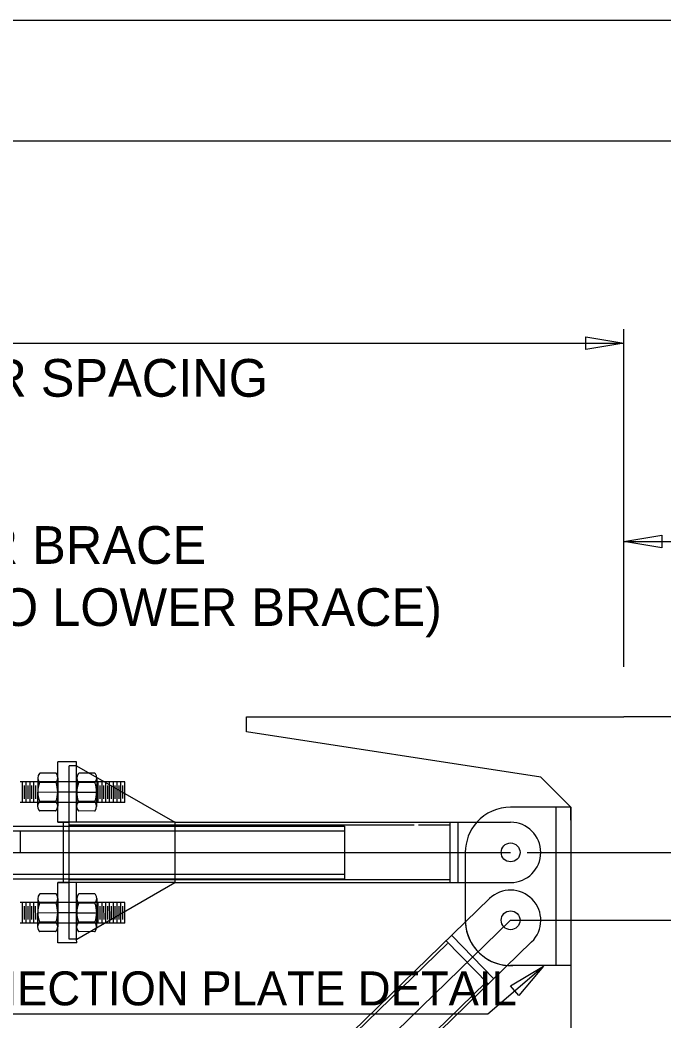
# Model space of a CAD drawing. Extents: x 0 to 45.3, y 0 to 31.4.
# Drawn here: x 11.86 to 15.41, y 23.8 to 29.33 of the extents above; entities that cross this region are included whole.
import ezdxf

# ---------------------------------------------------------------- set-up
doc = ezdxf.new("R2010")
doc.units = 0
for name, color, linetype in [('BORDER_ANNO_Cutsheet', 7, 'Continuous'), ('BRDG_ANNO_Anno-Sheet', 7, 'Continuous'), ('BRDG_ANNO_General-Notes', 7, 'Continuous'), ('BRDG_BASE_Dtlctrln', 7, 'Continuous'), ('BRDG_BASE_Hidden-Line', 7, 'Continuous'), ('BRDG_BASE_Obj-Line', 7, 'Continuous')]:
    doc.layers.add(name, color=color, linetype=linetype)

msp = doc.modelspace()

# ---------------------------------------------------------------- linework, layer by layer
at = {"layer": 'BORDER_ANNO_Cutsheet'}
msp.add_lwpolyline([(0, 29.3333), (45.3333, 29.3333), (45.3333, 0), (0, 0)], close=True, dxfattribs=at)
at = {"layer": 'BRDG_ANNO_Anno-Sheet'}
msp.add_lwpolyline([(2, 28.6667), (44.6667, 28.6667), (44.6667, 0.6667), (2, 0.6667)], close=True, dxfattribs=at)
at = {"layer": 'BRDG_ANNO_General-Notes'}
for p, q in [((15.1896, 25.7604), (15.1896, 27.6256)), ((8.7729, 27.5478), (15.1896, 27.5478)), ((14.9796, 27.5128), (14.9796, 27.5828)), ((14.9796, 27.5828), (15.1896, 27.5478)), ((15.1896, 27.5478), (14.9796, 27.5128)), ((15.1896, 26.4532), (15.3996, 26.4882)), ((15.1896, 26.4532), (20.0307, 26.4532)), ((15.3996, 26.4182), (15.1896, 26.4532)), ((15.3996, 26.4882), (15.3996, 26.4182)), ((14.6553, 24.7346), (17.9417, 24.7346)), ((14.5646, 24.3596), (17.9417, 24.3596)), ((14.4392, 23.8431), (14.7469, 24.1069)), ((14.5647, 23.9968), (14.7469, 24.1069)), ((14.7469, 24.1069), (14.6103, 23.9436)), ((14.6103, 23.9436), (14.5647, 23.9968)), ((10.0035, 23.8431), (14.4392, 23.8431))]:
    msp.add_line(p, q, dxfattribs=at)
at = {"layer": 'BRDG_BASE_Dtlctrln'}
for p, q in [((9.3979, 24.7346), (14.0555, 24.7346)), ((14.0555, 24.7346), (14.5646, 24.7346)), ((13.7136, 23.5335), (14.5646, 24.3596))]:
    msp.add_line(p, q, dxfattribs=at)
at = {"layer": 'BRDG_BASE_Hidden-Line'}
for p, q in [((12.0533, 25.1722), (11.9667, 25.1727)), ((12.2685, 25.1716), (12.1819, 25.172)), ((11.9544, 25.1467), (11.9533, 24.9903)), ((12.0549, 25.1202), (11.9641, 25.1207)), ((12.0649, 25.147), (12.0642, 24.9897)), ((12.1696, 25.1459), (12.1685, 24.9896)), ((12.2701, 25.1195), (12.1793, 25.12)), ((12.2801, 25.1462), (12.2794, 24.9891)), ((11.9536, 25.0685), (12.0647, 25.0679)), ((12.1689, 25.0679), (12.2799, 25.0672)), ((12.0545, 25.0161), (11.9634, 25.0166)), ((12.2697, 25.0154), (12.1786, 25.0159)), ((12.0518, 24.964), (11.9651, 24.9644)), ((12.267, 24.9633), (12.1803, 24.9637)), ((12.0533, 24.5056), (11.9667, 24.5061)), ((12.2685, 24.505), (12.1819, 24.5054)), ((11.9544, 24.4801), (11.9533, 24.3237)), ((12.0549, 24.4535), (11.9641, 24.4541)), ((12.0649, 24.4804), (12.0642, 24.3231)), ((12.1696, 24.4794), (12.1685, 24.323)), ((12.2701, 24.4529), (12.1793, 24.4534)), ((12.2802, 24.4797), (12.2794, 24.3225)), ((11.9536, 24.402), (12.0647, 24.4013)), ((12.1689, 24.4013), (12.2799, 24.4006)), ((12.0545, 24.3495), (11.9634, 24.3501)), ((12.2698, 24.3489), (12.1786, 24.3494)), ((12.0518, 24.2974), (11.9651, 24.2978)), ((12.267, 24.2967), (12.1804, 24.2971))]:
    msp.add_line(p, q, dxfattribs=at)
for centre, radius, start, end in [((11.9939, 25.1462), 0.0394, 141.172, 220.8452), ((11.9667, 25.1683), 0.00434, 89.6962, 144.3514), ((12.0533, 25.1679), 0.00434, 34.166, 89.6962), ((12.0254, 25.1467), 0.0394, 318.5472, 36.8383), ((12.2091, 25.1455), 0.0394, 141.172, 220.8452), ((12.1819, 25.1676), 0.00434, 89.6962, 144.3514), ((12.2685, 25.1672), 0.00434, 34.166, 89.6962), ((12.2406, 25.146), 0.0394, 318.5472, 36.8383), ((12.1002, 25.0674), 0.1461, 158.7225, 200.4789), ((11.9182, 25.0691), 0.1461, 338.9136, 20.6699), ((12.3154, 25.0667), 0.1461, 158.7225, 200.4789), ((12.1334, 25.0684), 0.1461, 338.9136, 20.6699), ((11.9928, 24.9902), 0.0394, 138.4514, 217.3425), ((12.0248, 24.9907), 0.0394, 320.6611, 40.9411), ((12.208, 24.9895), 0.0394, 138.4514, 217.3425), ((12.24, 24.99), 0.0394, 320.6611, 40.9411), ((11.9651, 24.9687), 0.00434, 214.4962, 269.6962), ((12.0517, 24.9683), 0.00434, 269.6962, 324.0466), ((12.1803, 24.9681), 0.00434, 214.4962, 269.6962), ((12.2669, 24.9676), 0.00434, 269.6962, 324.0466), ((11.9939, 24.4796), 0.0394, 141.172, 220.8452), ((11.9667, 24.5017), 0.00434, 89.6962, 144.3514), ((12.0533, 24.5013), 0.00434, 34.166, 89.6962), ((12.0254, 24.4801), 0.0394, 318.5472, 36.8383), ((12.2091, 24.4789), 0.0394, 141.172, 220.8452), ((12.182, 24.5011), 0.00434, 89.6962, 144.3514), ((12.2685, 24.5006), 0.00434, 34.166, 89.6962), ((12.2406, 24.4794), 0.0394, 318.5472, 36.8383), ((12.1002, 24.4008), 0.1461, 158.7225, 200.4789), ((11.9182, 24.4025), 0.1461, 338.9136, 20.6699), ((12.3155, 24.4002), 0.1461, 158.7225, 200.4789), ((12.1334, 24.4018), 0.1461, 338.9136, 20.6699), ((11.9928, 24.3236), 0.0394, 138.4514, 217.3425), ((12.0248, 24.3241), 0.0394, 320.6611, 40.9411), ((12.2081, 24.3229), 0.0394, 138.4514, 217.3425), ((12.24, 24.3234), 0.0394, 320.6611, 40.9411), ((11.9651, 24.3022), 0.00434, 214.4962, 269.6962), ((12.0517, 24.3017), 0.00434, 269.6962, 324.0466), ((12.1803, 24.3015), 0.00434, 214.4962, 269.6962), ((12.2669, 24.301), 0.00434, 269.6962, 324.0466)]:
    msp.add_arc(centre, radius, start, end, dxfattribs=at)
at = {"layer": 'BRDG_BASE_Obj-Line'}
for p, q in [((12.1689, 25.2346), (12.0647, 25.2346)), ((12.0647, 24.9012), (12.0647, 25.2346)), ((12.1689, 25.2137), (12.1689, 25.2346)), ((12.0533, 25.1722), (11.9667, 25.1727)), ((12.1273, 24.2554), (12.1272, 25.2137)), ((12.1689, 25.2137), (12.1272, 25.2137)), ((12.1689, 25.2137), (12.7106, 24.9012)), ((12.1689, 24.9012), (12.1689, 25.2137)), ((12.2685, 25.1716), (12.1819, 25.172)), ((11.9484, 25.1252), (11.8565, 25.1251)), ((11.8697, 25.0105), (11.8697, 25.1251)), ((11.8906, 25.0105), (11.8905, 25.1251)), ((11.9114, 25.0106), (11.9114, 25.1252)), ((11.9322, 25.0106), (11.9322, 25.1252)), ((12.3228, 25.1254), (11.9482, 25.1252)), ((11.9544, 25.1467), (11.9533, 24.9903)), ((12.0549, 25.1202), (11.9641, 25.1207)), ((12.0649, 25.147), (12.0642, 24.9897)), ((12.1696, 25.1459), (12.1685, 24.9896)), ((12.2701, 25.1195), (12.1793, 25.12)), ((12.2801, 25.1462), (12.2794, 24.9891)), ((12.2885, 25.0107), (12.2884, 25.1253)), ((12.3093, 25.0107), (12.3093, 25.1253)), ((12.4343, 25.1254), (12.3228, 25.1254)), ((12.3302, 25.1195), (12.3302, 25.1253)), ((12.3302, 25.0107), (12.3302, 25.1195)), ((12.351, 25.108), (12.351, 25.1253)), ((12.351, 25.0107), (12.351, 25.108)), ((12.3718, 25.0969), (12.3718, 25.1253)), ((12.3927, 25.0836), (12.3926, 25.1253)), ((12.4135, 25.0716), (12.4135, 25.1253)), ((12.4343, 25.0608), (12.4343, 25.1254)), ((11.8802, 25.0314), (11.8802, 25.1043)), ((11.901, 25.0314), (11.901, 25.1043)), ((11.9219, 25.0314), (11.9218, 25.1043)), ((11.9427, 25.0314), (11.9427, 25.1043)), ((11.9536, 25.0685), (12.0647, 25.0679)), ((12.1689, 25.0679), (12.0647, 25.0679)), ((12.1689, 25.0679), (12.2799, 25.0672)), ((12.2781, 25.0315), (12.2781, 25.1044)), ((12.299, 25.0315), (12.2989, 25.1044)), ((12.3198, 25.0315), (12.3197, 25.1044)), ((12.3406, 25.0315), (12.3406, 25.1044)), ((12.3615, 25.0315), (12.3614, 25.1044)), ((12.3718, 25.0107), (12.3718, 25.0969)), ((12.3822, 25.0896), (12.3822, 25.1044)), ((12.3823, 25.0315), (12.3822, 25.0896)), ((12.3927, 25.0107), (12.3927, 25.0836)), ((12.4031, 25.0789), (12.4031, 25.1044)), ((12.4031, 25.0315), (12.4031, 25.0789)), ((12.4135, 25.0107), (12.4135, 25.0716)), ((12.4239, 25.0655), (12.4239, 25.1045)), ((12.424, 25.0316), (12.424, 25.0652)), ((12.4343, 25.0107), (12.4343, 25.0607)), ((11.949, 25.0106), (11.8564, 25.0105)), ((12.4343, 25.0107), (11.9496, 25.0106)), ((12.0545, 25.0161), (11.9634, 25.0166)), ((12.2697, 25.0154), (12.1786, 25.0159)), ((12.0518, 24.964), (11.9651, 24.9644)), ((12.267, 24.9633), (12.1803, 24.9637)), ((14.8979, 24.9846), (14.5646, 24.9846)), ((14.8146, 24.9846), (14.8146, 24.1096)), ((14.8979, 24.9846), (14.8979, 20.1622)), ((12.1316, 24.9012), (12.0644, 24.9012)), ((12.0645, 24.9012), (12.129, 24.9012)), ((12.096, 24.568), (12.096, 24.9012)), ((14.0321, 24.8855), (12.1315, 24.8856)), ((12.7127, 24.9012), (12.1316, 24.9012)), ((12.7106, 24.9014), (12.7106, 24.5681)), ((12.7106, 24.9012), (13.9148, 24.9012)), ((13.9148, 24.9012), (14.5646, 24.9012)), ((14.2312, 24.8855), (14.0555, 24.8855)), ((14.2313, 24.5679), (14.2312, 24.9012)), ((14.273, 24.9003), (14.273, 24.569)), ((14.38, 24.9012), (14.5646, 24.9012)), ((9.7313, 24.8543), (13.6479, 24.8544)), ((11.6183, 24.8804), (12.0972, 24.8804)), ((11.8564, 24.8484), (11.8564, 24.7346)), ((12.0972, 24.8804), (13.6479, 24.8805)), ((13.6479, 24.8805), (13.648, 24.5887)), ((12.2731, 24.7346), (12.2731, 24.7346)), ((12.5648, 24.7346), (12.5648, 24.7346)), ((14.3146, 24.7346), (14.3146, 24.5652)), ((9.7313, 24.6147), (13.6479, 24.6148)), ((11.6173, 24.5887), (12.096, 24.5887)), ((12.0647, 24.2346), (12.0647, 24.5679)), ((12.1273, 24.5679), (12.0647, 24.5679)), ((12.0647, 24.5679), (12.1289, 24.5679)), ((12.096, 24.5887), (13.648, 24.5887)), ((14.0555, 24.5833), (12.1316, 24.5835)), ((12.7127, 24.5678), (12.1316, 24.5679)), ((12.1689, 24.2551), (12.1689, 24.5679)), ((12.169, 24.2555), (12.7106, 24.5678)), ((12.7106, 24.5679), (14.0555, 24.5679)), ((14.2313, 24.5833), (14.0555, 24.5833)), ((14.0555, 24.5679), (14.5646, 24.5679)), ((14.3146, 24.5652), (14.3146, 24.3596)), ((12.0533, 24.5056), (11.9667, 24.5061)), ((12.2685, 24.505), (12.1819, 24.5054)), ((11.9484, 24.4585), (11.8565, 24.4584)), ((11.8697, 24.344), (11.8697, 24.4585)), ((11.8905, 24.344), (11.8905, 24.4585)), ((11.9114, 24.344), (11.9114, 24.4585)), ((11.9322, 24.344), (11.9322, 24.4585)), ((12.4345, 24.4587), (11.9484, 24.4585)), ((11.9544, 24.4801), (11.9533, 24.3237)), ((12.0549, 24.4535), (11.9641, 24.4541)), ((12.0649, 24.4804), (12.0642, 24.3231)), ((12.1696, 24.4794), (12.1685, 24.323)), ((12.2701, 24.4529), (12.1793, 24.4534)), ((12.2802, 24.4797), (12.2794, 24.3225)), ((12.2886, 24.3441), (12.2886, 24.4586)), ((12.3095, 24.3441), (12.3095, 24.4586)), ((12.3303, 24.3493), (12.3303, 24.4587)), ((12.3512, 24.3616), (12.3511, 24.4586)), ((12.372, 24.3729), (12.372, 24.4586)), ((12.3929, 24.3844), (12.3928, 24.4586)), ((12.4136, 24.3967), (12.4136, 24.4587)), ((12.4345, 24.4086), (12.4345, 24.4587)), ((14.316, 24.3506), (14.4485, 24.4792)), ((11.8802, 24.3648), (11.8802, 24.4377)), ((11.901, 24.3648), (11.9009, 24.4377)), ((11.9218, 24.3648), (11.9218, 24.4378)), ((11.9427, 24.3648), (11.9426, 24.4378)), ((11.9536, 24.402), (12.0647, 24.4013)), ((12.1689, 24.4013), (12.0647, 24.4013)), ((12.1689, 24.4013), (12.2799, 24.4006)), ((12.2991, 24.3648), (12.2991, 24.4378)), ((12.3199, 24.3648), (12.3198, 24.4378)), ((12.3407, 24.3649), (12.3407, 24.4378)), ((12.3616, 24.3649), (12.3615, 24.4378)), ((12.3824, 24.3789), (12.3823, 24.4378)), ((12.4032, 24.3915), (12.4032, 24.4379)), ((12.4032, 24.3649), (12.4032, 24.3915)), ((12.4137, 24.3441), (12.4136, 24.3967)), ((12.4241, 24.4028), (12.424, 24.4379)), ((12.4241, 24.3649), (12.4241, 24.4025)), ((12.4345, 24.3441), (12.4345, 24.4086)), ((11.949, 24.344), (11.8564, 24.344)), ((12.3221, 24.3441), (11.9498, 24.344)), ((12.0545, 24.3495), (11.9634, 24.3501)), ((12.2698, 24.3489), (12.1786, 24.3494)), ((12.4345, 24.3441), (12.323, 24.3441)), ((12.3303, 24.3441), (12.3303, 24.3493)), ((12.3512, 24.3441), (12.3512, 24.3616)), ((12.372, 24.3441), (12.372, 24.3729)), ((12.3824, 24.3649), (12.3824, 24.3789)), ((12.3928, 24.3441), (12.3929, 24.3844)), ((13.6053, 23.6606), (14.3158, 24.3503)), ((12.0518, 24.2974), (11.9651, 24.2978)), ((12.267, 24.2967), (12.1804, 24.2971)), ((12.169, 24.2346), (12.0647, 24.2346)), ((12.169, 24.2555), (12.1273, 24.2554)), ((12.169, 24.2346), (12.1689, 24.2551)), ((14.2161, 24.2316), (13.5019, 23.5382)), ((13.8298, 23.4139), (14.6808, 24.24)), ((14.4415, 24.0078), (14.2093, 24.2469)), ((14.2399, 24.2754), (14.4707, 24.0377)), ((14.8979, 24.1096), (14.5646, 24.1096)), ((14.4284, 24.0166), (13.819, 23.4249))]:
    msp.add_line(p, q, dxfattribs=at)
for points in [[(14.8979, 24.9124), (14.8979, 24.9846), (14.7312, 25.1512), (13.1062, 25.4012), (13.1062, 25.4846), (15.1896, 25.4846)], [(15.4812, 24.9124), (15.4812, 24.9846), (15.6479, 25.1512), (17.2729, 25.4012), (17.2729, 25.4846), (15.1896, 25.4846)]]:
    msp.add_lwpolyline(points, dxfattribs=at)
for centre in [(14.5646, 24.7346), (14.5646, 24.3596)]:
    msp.add_circle(centre, 0.0521, dxfattribs=at)
for centre, radius, start, end in [((11.9939, 25.1462), 0.0394, 141.172, 220.8452), ((11.9667, 25.1683), 0.00434, 89.6962, 144.3514), ((12.0533, 25.1679), 0.00434, 34.166, 89.6962), ((12.0254, 25.1467), 0.0394, 318.5472, 36.8383), ((12.2091, 25.1455), 0.0394, 141.172, 220.8452), ((12.1819, 25.1676), 0.00434, 89.6962, 144.3514), ((12.2685, 25.1672), 0.00434, 34.166, 89.6962), ((12.2406, 25.146), 0.0394, 318.5472, 36.8383), ((12.1002, 25.0674), 0.1461, 158.7225, 200.4789), ((11.9182, 25.0691), 0.1461, 338.9136, 20.6699), ((12.3154, 25.0667), 0.1461, 158.7225, 200.4789), ((12.1334, 25.0684), 0.1461, 338.9136, 20.6699), ((11.9928, 24.9902), 0.0394, 138.4514, 217.3425), ((12.0248, 24.9907), 0.0394, 320.6611, 40.9411), ((12.208, 24.9895), 0.0394, 138.4514, 217.3425), ((12.24, 24.99), 0.0394, 320.6611, 40.9411), ((11.9651, 24.9687), 0.00434, 214.4962, 269.6962), ((12.0517, 24.9683), 0.00434, 269.6962, 324.0466), ((12.1803, 24.9681), 0.00434, 214.4962, 269.6962), ((12.2669, 24.9676), 0.00434, 269.6962, 324.0466), ((14.5646, 24.7346), 0.25, 90, 138.1298), ((14.5646, 24.7346), 0.25, 138.1298, 180), ((14.5646, 24.7346), 0.1667, 270.0087, 90.0087), ((11.9939, 24.4796), 0.0394, 141.172, 220.8452), ((11.9667, 24.5017), 0.00434, 89.6962, 144.3514), ((12.0533, 24.5013), 0.00434, 34.166, 89.6962), ((12.0254, 24.4801), 0.0394, 318.5472, 36.8383), ((12.2091, 24.4789), 0.0394, 141.172, 220.8452), ((12.182, 24.5011), 0.00434, 89.6962, 144.3514), ((12.2685, 24.5006), 0.00434, 34.166, 89.6962), ((12.2406, 24.4794), 0.0394, 318.5472, 36.8383), ((14.5646, 24.3596), 0.1667, 314.1607, 134.1607), ((12.1002, 24.4008), 0.1461, 158.7225, 200.4789), ((11.9182, 24.4025), 0.1461, 338.9136, 20.6699), ((12.3155, 24.4002), 0.1461, 158.7225, 200.4789), ((12.1334, 24.4018), 0.1461, 338.9136, 20.6699), ((11.9928, 24.3236), 0.0394, 138.4514, 217.3425), ((12.0248, 24.3241), 0.0394, 320.6611, 40.9411), ((12.2081, 24.3229), 0.0394, 138.4514, 217.3425), ((12.24, 24.3234), 0.0394, 320.6611, 40.9411), ((14.5646, 24.3596), 0.25, 180, 263.4345), ((14.5646, 24.3596), 0.25, 183, 266.4345), ((11.9651, 24.3022), 0.00434, 214.4962, 269.6962), ((12.0517, 24.3017), 0.00434, 269.6962, 324.0466), ((12.1803, 24.3015), 0.00434, 214.4962, 269.6962), ((12.2669, 24.301), 0.00434, 269.6962, 324.0466), ((14.5646, 24.3596), 0.25, 266.4345, 273)]:
    msp.add_arc(centre, radius, start, end, dxfattribs=at)

# ---------------------------------------------------------------- texts
at = {"layer": 'BRDG_ANNO_General-Notes'}
for s, height, p in [('GIRDER SPACING', 0.208333, (10.8102, 27.2521)), ('UPPER BRACE', 0.208333, (10.8861, 26.3288)), ('(SIMILAR TO LOWER BRACE)', 0.208333, (10.285, 25.9856)), ('UPPER CONNECTION PLATE DETAIL', 0.1875, (10.1683, 23.8897))]:
    msp.add_text(s, height=height, dxfattribs=at).set_placement(p)

doc.saveas('drawing.dxf')
